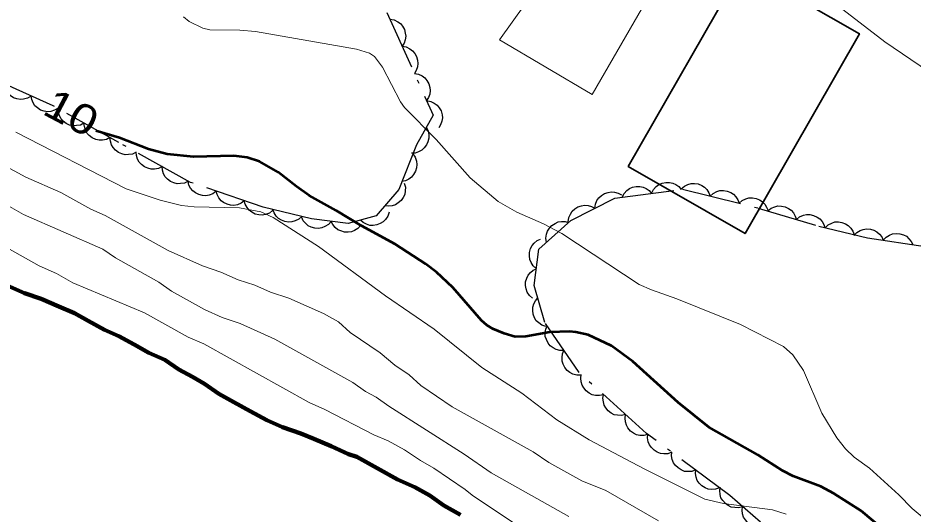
# Model space of a CAD drawing. Extents: x 356765 to 358572, y 5103174 to 5104650.
# Drawn here: x 357732.38 to 357777.43, y 5103444.76 to 5103469.73 of the extents above; entities that cross this region are included whole.
import ezdxf
from ezdxf.enums import TextEntityAlignment as Align

# ---------------------------------------------------------------- set-up
doc = ezdxf.new("R2010")
doc.units = 0
doc.header["$LTSCALE"] = 0.6
doc.linetypes.add('DOT_DASHED', pattern=[7.7, 5, -1.2, 0.3, -1.2])
for name, color, linetype, lineweight in [('1', 7, 'Continuous', 53), ('19', 7, 'Continuous', 13), ('2', 7, 'Continuous', 13), ('31', 7, 'Continuous', 70), ('4', 7, 'Continuous', 90), ('44', 7, 'Continuous', 25)]:
    doc.layers.add(name, color=color, linetype=linetype, lineweight=lineweight)

msp = doc.modelspace()

# ---------------------------------------------------------------- linework, layer by layer
at = {"layer": '1'}
msp.add_lwpolyline([(357775.96, 5103443.96), (357774.82, 5103444.92), (357773.44, 5103445.8), (357772.79, 5103446.15), (357771.39, 5103446.67), (357770.87, 5103446.94), (357769.62, 5103447.75), (357767.15, 5103449.13), (357765.61, 5103450.37), (357763.33, 5103452.44), (357762.25, 5103453.22), (357761.08, 5103453.78), (357760.46, 5103453.92), (357760.13, 5103453.95), (357759.14, 5103453.92), (357757.94, 5103453.69), (357757.4, 5103453.68), (357756.85, 5103453.84), (357756.28, 5103454.09), (357755.97, 5103454.26), (357755.7, 5103454.5), (357754.27, 5103456.17), (357753.44, 5103456.93), (357752.89, 5103457.36), (357751.36, 5103458.34), (357749.66, 5103459.26), (357748.4, 5103460.04), (357747.03, 5103460.8), (357746.39, 5103461.24), (357745.47, 5103461.97), (357744.53, 5103462.51), (357743.91, 5103462.7), (357743.25, 5103462.79), (357741.21, 5103462.74), (357739.88, 5103462.88), (357738.95, 5103463.13), (357737.49, 5103463.7), (357736.3, 5103464.05)], dxfattribs=at)
at = {"layer": '19'}
msp.add_lwpolyline([(357781.3, 5103464.94), (357776, 5103468.53), (357772.8, 5103471.01), (357769.83, 5103472.73), (357767.6, 5103473.47), (357766.17, 5103473), (357764.63, 5103471.7), (357761.28, 5103465.88), (357756.62, 5103468.62), (357759.88, 5103473.21), (357761.86, 5103476.72), (357762.43, 5103478.88), (357761.19, 5103480.5), (357758.56, 5103482.46), (357753.03, 5103485.82), (357754.87, 5103489.01), (357759.3, 5103486.66), (357759.77, 5103487.54), (357760.06, 5103488.08), (357762.04, 5103491.48)], dxfattribs=at)
at = {"layer": '2'}
for points in [[(357778.89, 5103443.78), (357777.38, 5103445.04), (357776.71, 5103445.73), (357775.23, 5103447.07), (357774.47, 5103447.63), (357774.02, 5103448.05), (357773.6, 5103448.59), (357772.84, 5103449.84), (357771.92, 5103451.98), (357771.37, 5103452.78), (357770.91, 5103453.2), (357768.75, 5103454.3), (357765.54, 5103455.59), (357764.27, 5103456.04), (357763.65, 5103456.32), (357759.75, 5103458.88), (357758.83, 5103459.36), (357757.49, 5103459.95), (357756.55, 5103460.49), (357755.13, 5103461.68), (357753.43, 5103463.61), (357751.84, 5103465.22), (357751.63, 5103465.5), (357750.73, 5103467.25), (357750.32, 5103467.78), (357750.07, 5103467.95), (357749.42, 5103468.16), (357744.33, 5103469.05), (357743.55, 5103469.11), (357742.04, 5103469.13), (357741.68, 5103469.21), (357741, 5103469.55), (357740.71, 5103469.78)], [(357764.61, 5103444.42), (357761.97, 5103445.94), (357760.75, 5103446.43), (357759.09, 5103447.35), (357758.3, 5103447.89), (357754.23, 5103450.16), (357752.65, 5103451.23), (357752.06, 5103451.76), (357751.35, 5103452.25), (357750.6, 5103452.87), (357749.1, 5103453.9), (357748.51, 5103454.43), (357747.75, 5103454.85), (357746.01, 5103455.62), (357745.09, 5103455.93), (357744.3, 5103456.28), (357743.46, 5103456.55), (357742.59, 5103456.94), (357741.67, 5103457.25), (357739.93, 5103458.03), (357736.76, 5103459.79), (357736.04, 5103460.1), (357734.53, 5103460.94), (357732.78, 5103461.71), (357726.63, 5103465.04)], [(357771.04, 5103444.75), (357770.35, 5103444.98), (357767.89, 5103445.3), (357766.94, 5103445.51), (357763.89, 5103447.04), (357761.13, 5103448.5), (357759.5, 5103449.51), (357757.74, 5103450.84), (357755.73, 5103452.13), (357753.32, 5103454.07), (357750.88, 5103455.74), (357747.5, 5103458.22), (357745.23, 5103459.68), (357744.6, 5103459.97), (357743.53, 5103460.18), (357741.24, 5103460.22), (357740.61, 5103460.29), (357739.53, 5103460.55), (357737.83, 5103461.13), (357732.27, 5103463.98)], [(357731.83, 5103460.3), (357732.66, 5103459.83), (357736.65, 5103458.1), (357737.29, 5103457.65), (357739.47, 5103456.43), (357740.11, 5103455.98), (357741.77, 5103455.05), (357742.65, 5103454.66), (357743.56, 5103454.35), (357745.31, 5103453.57), (357749.23, 5103451.39), (357749.87, 5103450.93), (357750.4, 5103450.64), (357751.04, 5103450.19), (357754.84, 5103447.77), (357756.19, 5103446.83), (357760.11, 5103444.64)], [(357731.25, 5103458.48), (357733.44, 5103457.26), (357734.31, 5103456.87), (357735.14, 5103456.4), (357738.75, 5103454.88), (357740.94, 5103453.66), (357741.74, 5103453.32), (357747.03, 5103450.37), (357747.83, 5103450.02), (357750.29, 5103448.75), (357751.01, 5103448.45), (357751.84, 5103447.99), (357752.63, 5103447.45), (357753.31, 5103447.07), (357754.89, 5103445.99), (357755.23, 5103445.71), (357762.45, 5103440.9)]]:
    msp.add_lwpolyline(points, dxfattribs=at)
at = {"layer": '31', "lineweight": 35}
msp.add_lwpolyline([(357768.85, 5103472.3), (357763.09, 5103462.26), (357768.97, 5103458.88), (357774.73, 5103468.93), (357768.85, 5103472.3)], close=True, dxfattribs=at)
at = {"layer": '4'}
for points in [[(357731.84, 5103456.26), (357732.71, 5103455.87), (357733.55, 5103455.6), (357734.43, 5103455.21), (357735.22, 5103454.87), (357735.91, 5103454.49), (357736.74, 5103454.03), (357737.46, 5103453.72), (357738.22, 5103453.3), (357738.97, 5103452.88), (357739.77, 5103452.53), (357740.48, 5103452.04), (357741.16, 5103451.66), (357741.77, 5103451.32), (357742.48, 5103450.82), (357743.24, 5103450.4), (357744.07, 5103449.94), (357744.9, 5103449.48), (357745.7, 5103449.13), (357746.62, 5103448.82), (357747.27, 5103448.55)], [(357747.27, 5103448.55), (357748.14, 5103448.17), (357749.01, 5103447.78), (357749.43, 5103447.64), (357751.48, 5103446.5), (357752.35, 5103446.12), (357753.11, 5103445.69), (357753.82, 5103445.2), (357754.65, 5103444.73)]]:
    msp.add_lwpolyline(points, dxfattribs=at)
at = {"layer": '44', "linetype": 'DOT_DASHED'}
for points in [[(357750.95, 5103470.01), (357753.27, 5103464.84), (357752.43, 5103463.35), (357751.55, 5103461.1), (357750.41, 5103459.77), (357749, 5103459.38), (357747.16, 5103459.62), (357744.72, 5103460.2), (357741.07, 5103461.45), (357737.46, 5103463.46), (357734.15, 5103465.3), (357723.12, 5103470.28)], [(357773.24, 5103441.33), (357768.2, 5103445.7), (357764.02, 5103448.81), (357760.62, 5103451.88), (357758.89, 5103454.41), (357758.36, 5103456.27), (357758.6, 5103458.09), (357760.21, 5103459.54), (357762.42, 5103460.66), (357765.83, 5103461.11), (357769.64, 5103460.16), (357772.68, 5103459.25), (357775.13, 5103458.67), (357778.04, 5103458.22)]]:
    msp.add_lwpolyline(points, dxfattribs=at)
at = {"layer": '44'}
for points in [[(357751.1, 5103469.67), (357751.31, 5103469.64), (357751.49, 5103469.54), (357751.63, 5103469.45), (357751.74, 5103469.31), (357751.83, 5103469.15), (357751.87, 5103468.97), (357751.9, 5103468.81), (357751.87, 5103468.63), (357751.81, 5103468.46), (357751.72, 5103468.3)], [(357751.72, 5103468.3), (357751.92, 5103468.27), (357752.1, 5103468.17), (357752.24, 5103468.08), (357752.35, 5103467.94), (357752.44, 5103467.78), (357752.49, 5103467.6), (357752.51, 5103467.44), (357752.48, 5103467.26), (357752.42, 5103467.09), (357752.33, 5103466.93)], [(357752.33, 5103466.93), (357752.54, 5103466.9), (357752.72, 5103466.81), (357752.85, 5103466.71), (357752.96, 5103466.58), (357753.05, 5103466.41), (357753.1, 5103466.23), (357753.13, 5103466.07), (357753.1, 5103465.89), (357753.04, 5103465.72), (357752.94, 5103465.57)], [(357733.04, 5103465.8), (357732.86, 5103465.69), (357732.66, 5103465.64), (357732.5, 5103465.62), (357732.32, 5103465.65), (357732.15, 5103465.71), (357731.99, 5103465.82), (357731.87, 5103465.92), (357731.77, 5103466.07), (357731.7, 5103466.24), (357731.67, 5103466.42)], [(357734.4, 5103465.19), (357734.22, 5103465.08), (357734.03, 5103465.02), (357733.86, 5103465), (357733.69, 5103465.03), (357733.52, 5103465.09), (357733.36, 5103465.2), (357733.23, 5103465.31), (357733.14, 5103465.46), (357733.07, 5103465.63), (357733.04, 5103465.8)], [(357752.94, 5103465.57), (357753.15, 5103465.53), (357753.33, 5103465.44), (357753.47, 5103465.34), (357753.58, 5103465.21), (357753.67, 5103465.05), (357753.72, 5103464.86), (357753.74, 5103464.7), (357753.71, 5103464.53), (357753.65, 5103464.35), (357753.56, 5103464.2)], [(357735.7, 5103464.44), (357735.52, 5103464.34), (357735.32, 5103464.31), (357735.15, 5103464.3), (357734.98, 5103464.34), (357734.81, 5103464.42), (357734.66, 5103464.54), (357734.55, 5103464.65), (357734.47, 5103464.81), (357734.41, 5103464.99), (357734.39, 5103465.17)], [(357737.01, 5103463.71), (357736.83, 5103463.61), (357736.63, 5103463.58), (357736.46, 5103463.57), (357736.29, 5103463.61), (357736.12, 5103463.69), (357735.97, 5103463.81), (357735.86, 5103463.92), (357735.78, 5103464.08), (357735.72, 5103464.26), (357735.7, 5103464.44)], [(357752.92, 5103464.23), (357753.02, 5103464.04), (357753.05, 5103463.84), (357753.06, 5103463.67), (357753.01, 5103463.5), (357752.94, 5103463.34), (357752.82, 5103463.19), (357752.7, 5103463.07), (357752.54, 5103462.99), (357752.37, 5103462.93), (357752.19, 5103462.92)], [(357738.32, 5103462.98), (357738.14, 5103462.88), (357737.94, 5103462.85), (357737.77, 5103462.84), (357737.6, 5103462.89), (357737.43, 5103462.96), (357737.28, 5103463.08), (357737.17, 5103463.2), (357737.09, 5103463.35), (357737.03, 5103463.53), (357737.01, 5103463.71)], [(357739.64, 5103462.25), (357739.45, 5103462.15), (357739.25, 5103462.12), (357739.08, 5103462.11), (357738.91, 5103462.16), (357738.74, 5103462.23), (357738.6, 5103462.35), (357738.48, 5103462.47), (357738.4, 5103462.62), (357738.34, 5103462.8), (357738.32, 5103462.98)], [(357752.25, 5103462.89), (357752.37, 5103462.72), (357752.43, 5103462.52), (357752.46, 5103462.36), (357752.44, 5103462.19), (357752.39, 5103462.01), (357752.29, 5103461.85), (357752.19, 5103461.71), (357752.05, 5103461.61), (357751.88, 5103461.53), (357751.7, 5103461.49)], [(357740.95, 5103461.52), (357740.76, 5103461.42), (357740.56, 5103461.39), (357740.39, 5103461.38), (357740.22, 5103461.43), (357740.06, 5103461.5), (357739.91, 5103461.62), (357739.79, 5103461.74), (357739.71, 5103461.89), (357739.65, 5103462.07), (357739.64, 5103462.25)], [(357742.35, 5103461.01), (357742.19, 5103460.88), (357742, 5103460.81), (357741.84, 5103460.78), (357741.66, 5103460.79), (357741.48, 5103460.84), (357741.31, 5103460.93), (357741.18, 5103461.02), (357741.07, 5103461.16), (357740.98, 5103461.32), (357740.94, 5103461.5)], [(357751.82, 5103461.42), (357751.88, 5103461.22), (357751.87, 5103461.02), (357751.85, 5103460.85), (357751.77, 5103460.69), (357751.66, 5103460.54), (357751.52, 5103460.42), (357751.38, 5103460.33), (357751.21, 5103460.28), (357751.03, 5103460.26), (357750.85, 5103460.28)], [(357764.27, 5103460.9), (357764.36, 5103461.09), (357764.5, 5103461.24), (357764.63, 5103461.34), (357764.8, 5103461.41), (357764.98, 5103461.45), (357765.17, 5103461.44), (357765.33, 5103461.42), (357765.49, 5103461.34), (357765.64, 5103461.24), (357765.76, 5103461.1)], [(357765.76, 5103461.13), (357765.92, 5103461.27), (357766.1, 5103461.35), (357766.26, 5103461.4), (357766.43, 5103461.4), (357766.62, 5103461.38), (357766.79, 5103461.3), (357766.93, 5103461.22), (357767.05, 5103461.09), (357767.15, 5103460.93), (357767.22, 5103460.76)], [(357743.77, 5103460.52), (357743.61, 5103460.4), (357743.42, 5103460.33), (357743.25, 5103460.29), (357743.08, 5103460.31), (357742.9, 5103460.35), (357742.73, 5103460.44), (357742.6, 5103460.53), (357742.49, 5103460.67), (357742.4, 5103460.84), (357742.35, 5103461.01)], [(357761.41, 5103460.15), (357761.44, 5103460.36), (357761.52, 5103460.54), (357761.61, 5103460.68), (357761.74, 5103460.8), (357761.89, 5103460.9), (357762.08, 5103460.95), (357762.24, 5103460.98), (357762.41, 5103460.96), (357762.59, 5103460.91), (357762.75, 5103460.83)], [(357762.78, 5103460.71), (357762.88, 5103460.89), (357763.02, 5103461.04), (357763.15, 5103461.15), (357763.31, 5103461.21), (357763.49, 5103461.25), (357763.68, 5103461.25), (357763.84, 5103461.22), (357764, 5103461.15), (357764.15, 5103461.04), (357764.27, 5103460.9)], [(357767.22, 5103460.76), (357767.37, 5103460.9), (357767.55, 5103460.99), (357767.71, 5103461.04), (357767.89, 5103461.04), (357768.07, 5103461.01), (357768.25, 5103460.94), (357768.39, 5103460.86), (357768.51, 5103460.73), (357768.61, 5103460.57), (357768.67, 5103460.4)], [(357745.19, 5103460.04), (357745.03, 5103459.91), (357744.84, 5103459.84), (357744.67, 5103459.81), (357744.5, 5103459.82), (357744.32, 5103459.86), (357744.15, 5103459.96), (357744.02, 5103460.05), (357743.91, 5103460.19), (357743.82, 5103460.35), (357743.77, 5103460.52)], [(357768.67, 5103460.4), (357768.83, 5103460.54), (357769.01, 5103460.63), (357769.17, 5103460.68), (357769.34, 5103460.68), (357769.53, 5103460.65), (357769.7, 5103460.57), (357769.84, 5103460.49), (357769.96, 5103460.36), (357770.06, 5103460.21), (357770.13, 5103460.04)], [(357746.67, 5103459.74), (357746.51, 5103459.6), (357746.33, 5103459.51), (357746.17, 5103459.46), (357746, 5103459.45), (357745.81, 5103459.48), (357745.64, 5103459.55), (357745.49, 5103459.63), (357745.37, 5103459.76), (357745.27, 5103459.92), (357745.21, 5103460.08)], [(357760.07, 5103459.47), (357760.1, 5103459.68), (357760.18, 5103459.86), (357760.27, 5103460), (357760.4, 5103460.12), (357760.56, 5103460.22), (357760.74, 5103460.27), (357760.9, 5103460.31), (357761.07, 5103460.29), (357761.25, 5103460.24), (357761.41, 5103460.15)], [(357770.12, 5103460.02), (357770.28, 5103460.15), (357770.47, 5103460.23), (357770.63, 5103460.27), (357770.81, 5103460.26), (357770.99, 5103460.22), (357771.16, 5103460.14), (357771.3, 5103460.05), (357771.41, 5103459.92), (357771.5, 5103459.76), (357771.56, 5103459.59)], [(357748.14, 5103459.49), (357748.01, 5103459.34), (357747.83, 5103459.23), (357747.68, 5103459.16), (357747.51, 5103459.14), (357747.32, 5103459.15), (357747.14, 5103459.2), (357746.99, 5103459.27), (357746.86, 5103459.38), (357746.74, 5103459.52), (357746.66, 5103459.69)], [(357751.06, 5103459.95), (357750.99, 5103459.75), (357750.87, 5103459.59), (357750.76, 5103459.47), (357750.61, 5103459.38), (357750.44, 5103459.31), (357750.25, 5103459.29), (357750.08, 5103459.29), (357749.92, 5103459.35), (357749.75, 5103459.43), (357749.61, 5103459.55)], [(357771.56, 5103459.59), (357771.72, 5103459.72), (357771.91, 5103459.8), (357772.07, 5103459.84), (357772.24, 5103459.83), (357772.42, 5103459.79), (357772.6, 5103459.71), (357772.73, 5103459.62), (357772.85, 5103459.49), (357772.94, 5103459.33), (357772.99, 5103459.16)], [(357749.63, 5103459.3), (357749.49, 5103459.14), (357749.32, 5103459.03), (357749.17, 5103458.97), (357748.99, 5103458.95), (357748.81, 5103458.95), (357748.63, 5103459.01), (357748.48, 5103459.07), (357748.34, 5103459.19), (357748.22, 5103459.33), (357748.14, 5103459.49)], [(357758.98, 5103458.43), (357758.95, 5103458.64), (357758.98, 5103458.84), (357759.03, 5103459), (357759.13, 5103459.15), (357759.25, 5103459.28), (357759.41, 5103459.38), (357759.56, 5103459.46), (357759.73, 5103459.48), (357759.92, 5103459.48), (357760.09, 5103459.44)], [(357773, 5103459.17), (357773.15, 5103459.32), (357773.34, 5103459.4), (357773.49, 5103459.46), (357773.67, 5103459.46), (357773.85, 5103459.43), (357774.03, 5103459.36), (357774.17, 5103459.28), (357774.29, 5103459.15), (357774.39, 5103459), (357774.46, 5103458.83)], [(357774.45, 5103458.78), (357774.59, 5103458.93), (357774.77, 5103459.03), (357774.92, 5103459.09), (357775.09, 5103459.11), (357775.28, 5103459.1), (357775.46, 5103459.04), (357775.61, 5103458.97), (357775.74, 5103458.85), (357775.85, 5103458.71), (357775.93, 5103458.55)], [(357775.93, 5103458.55), (357776.07, 5103458.7), (357776.25, 5103458.8), (357776.4, 5103458.87), (357776.58, 5103458.88), (357776.76, 5103458.87), (357776.94, 5103458.81), (357777.09, 5103458.74), (357777.22, 5103458.62), (357777.34, 5103458.48), (357777.41, 5103458.32)], [(357758.47, 5103457.11), (357758.31, 5103457.25), (357758.21, 5103457.42), (357758.14, 5103457.57), (357758.12, 5103457.75), (357758.13, 5103457.93), (357758.18, 5103458.12), (357758.25, 5103458.27), (357758.36, 5103458.4), (357758.51, 5103458.52), (357758.67, 5103458.6)], [(357758.27, 5103455.62), (357758.12, 5103455.76), (357758.01, 5103455.93), (357757.95, 5103456.09), (357757.92, 5103456.26), (357757.93, 5103456.44), (357757.99, 5103456.63), (357758.05, 5103456.78), (357758.17, 5103456.91), (357758.31, 5103457.03), (357758.47, 5103457.11)], [(357758.95, 5103454.2), (357758.75, 5103454.26), (357758.59, 5103454.38), (357758.46, 5103454.49), (357758.37, 5103454.64), (357758.31, 5103454.82), (357758.29, 5103455.01), (357758.29, 5103455.17), (357758.34, 5103455.34), (357758.42, 5103455.5), (357758.54, 5103455.64)], [(357759.86, 5103452.99), (357759.65, 5103452.99), (357759.46, 5103453.05), (357759.31, 5103453.12), (357759.17, 5103453.23), (357759.06, 5103453.37), (357758.98, 5103453.55), (357758.92, 5103453.7), (357758.92, 5103453.88), (357758.95, 5103454.06), (357759.01, 5103454.23)], [(357760.71, 5103451.75), (357760.5, 5103451.75), (357760.3, 5103451.81), (357760.15, 5103451.88), (357760.02, 5103451.99), (357759.9, 5103452.14), (357759.82, 5103452.31), (357759.77, 5103452.46), (357759.77, 5103452.64), (357759.79, 5103452.82), (357759.86, 5103452.99)], [(357761.85, 5103450.77), (357761.64, 5103450.72), (357761.44, 5103450.73), (357761.28, 5103450.76), (357761.12, 5103450.84), (357760.98, 5103450.96), (357760.86, 5103451.11), (357760.77, 5103451.24), (357760.73, 5103451.41), (357760.71, 5103451.6), (357760.73, 5103451.78)], [(357762.96, 5103449.77), (357762.76, 5103449.72), (357762.55, 5103449.73), (357762.39, 5103449.76), (357762.24, 5103449.84), (357762.09, 5103449.95), (357761.97, 5103450.1), (357761.88, 5103450.24), (357761.84, 5103450.41), (357761.82, 5103450.59), (357761.85, 5103450.77)], [(357764.07, 5103448.76), (357763.87, 5103448.71), (357763.67, 5103448.72), (357763.51, 5103448.75), (357763.35, 5103448.83), (357763.2, 5103448.94), (357763.08, 5103449.1), (357763, 5103449.23), (357762.95, 5103449.4), (357762.94, 5103449.59), (357762.96, 5103449.77)], [(357765.28, 5103447.87), (357765.08, 5103447.8), (357764.88, 5103447.79), (357764.72, 5103447.81), (357764.55, 5103447.87), (357764.4, 5103447.97), (357764.26, 5103448.11), (357764.16, 5103448.24), (357764.1, 5103448.4), (357764.07, 5103448.59), (357764.08, 5103448.77)], [(357766.49, 5103446.98), (357766.29, 5103446.91), (357766.08, 5103446.9), (357765.92, 5103446.91), (357765.76, 5103446.98), (357765.6, 5103447.08), (357765.47, 5103447.21), (357765.37, 5103447.34), (357765.31, 5103447.51), (357765.27, 5103447.69), (357765.28, 5103447.87)], [(357767.69, 5103446.08), (357767.49, 5103446.01), (357767.29, 5103446), (357767.12, 5103446.02), (357766.96, 5103446.08), (357766.8, 5103446.18), (357766.67, 5103446.32), (357766.57, 5103446.45), (357766.51, 5103446.61), (357766.48, 5103446.8), (357766.49, 5103446.98)], [(357768.85, 5103445.13), (357768.65, 5103445.08), (357768.45, 5103445.09), (357768.28, 5103445.11), (357768.13, 5103445.19), (357767.98, 5103445.3), (357767.85, 5103445.45), (357767.76, 5103445.58), (357767.72, 5103445.75), (357767.7, 5103445.94), (357767.72, 5103446.12)], [(357769.99, 5103444.15), (357769.78, 5103444.1), (357769.58, 5103444.1), (357769.42, 5103444.13), (357769.26, 5103444.21), (357769.11, 5103444.32), (357768.99, 5103444.47), (357768.9, 5103444.6), (357768.85, 5103444.77), (357768.83, 5103444.96), (357768.85, 5103445.13)]]:
    msp.add_lwpolyline(points, dxfattribs=at)

# ---------------------------------------------------------------- texts
at = {"layer": '1', "width": 1.2}
msp.add_text('10', height=1.5, rotation=332.085, dxfattribs=at).set_placement((357734.7189, 5103464.2995), align=Align.CENTER)

doc.saveas('drawing.dxf')
